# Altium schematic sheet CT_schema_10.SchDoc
size 391 x 278 mm
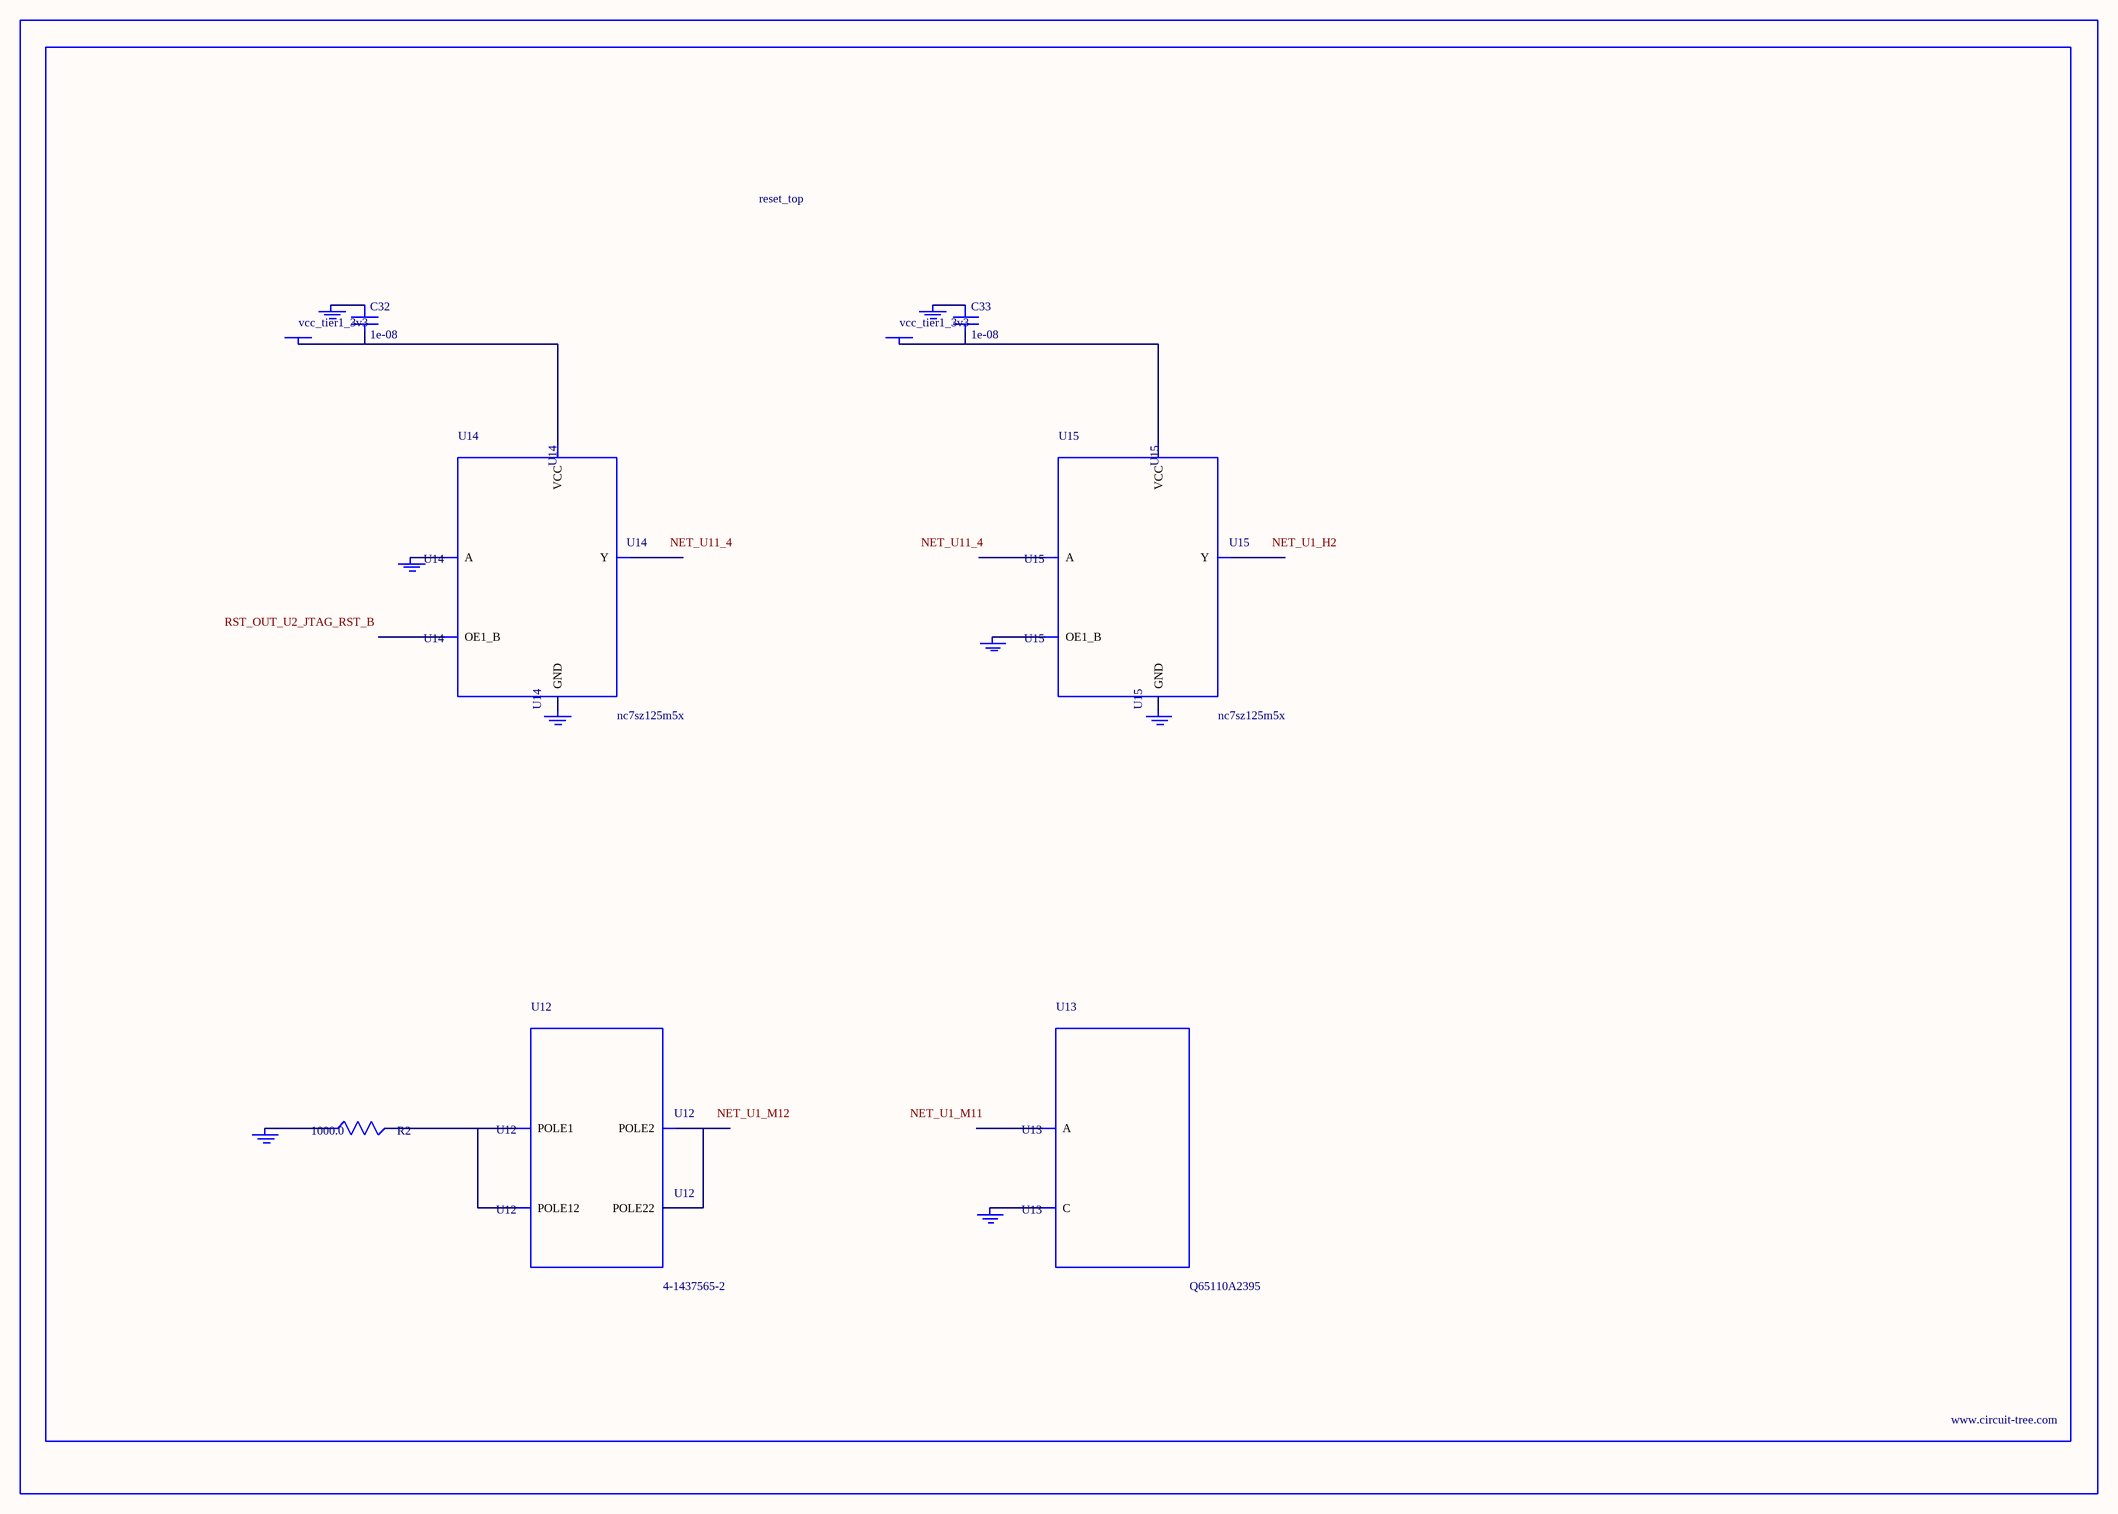
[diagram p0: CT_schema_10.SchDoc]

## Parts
BORDER9  (no value)
C32  1e-08  [C0402]
C33  1e-08  [C0402]
GND_INSTANCE_9_0  (no value)
GND_INSTANCE_9_1  (no value)
GND_INSTANCE_9_2  (no value)
GND_INSTANCE_9_3  (no value)
GND_INSTANCE_9_4  (no value)
GND_INSTANCE_9_5  (no value)
GND_INSTANCE_9_6  (no value)
GND_INSTANCE_9_7  (no value)
POWER_INSTANCE_9_0  vcc_tier1_3v3
POWER_INSTANCE_9_1  vcc_tier1_3v3
R2  1000.0  [R0603]
U12  4-1437565-2  [SW_4-1437565-2]
U13  Q65110A2395  [LGM67K-G1J2-24-Z]
U14  nc7sz125m5x  [NC7SZ125M5X]
U15  nc7sz125m5x  [NC7SZ125M5X]

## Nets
NetC32_1: C32.1 GND_INSTANCE_9_2.0(GND)
NetC32_2: C32.2 POWER_INSTANCE_9_0.0(PWR) U14.5(VCC)
NetC33_1: C33.1 GND_INSTANCE_9_5.0(GND)
NetC33_2: C33.2 POWER_INSTANCE_9_1.0(PWR) U15.5(VCC)
NetGND_INSTANCE_9_0_0: GND_INSTANCE_9_0.0(GND) R2.1
NetGND_INSTANCE_9_1_0: GND_INSTANCE_9_1.0(GND) U13.C
NetGND_INSTANCE_9_3_0: GND_INSTANCE_9_3.0(GND) U14.2(A)
NetGND_INSTANCE_9_4_0: GND_INSTANCE_9_4.0(GND) U14.3(GND)
NetGND_INSTANCE_9_6_0: GND_INSTANCE_9_6.0(GND) U15.1(OE1_B)
NetGND_INSTANCE_9_7_0: GND_INSTANCE_9_7.0(GND) U15.3(GND)
NetR2_2: R2.2 U12.1(POLE1) U12.2(POLE12)
NetU12_3: U12.3(POLE2) U12.4(POLE22)

Not connected (* = marked no-connect by the designer): U13 A; U14 1(OE1_B) 4(Y); U15 2(A) 4(Y)

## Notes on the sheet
- Labels drawn without touching a wire or pin: NET_U1_H2, NET_U1_M11, NET_U1_M12, NET_U11_4, RST_OUT_U2_JTAG_RST_B

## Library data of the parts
BORDER9 = BORDER_PAGE9
C32 C33 = C0402C103K3RAC
GND_INSTANCE_9_0-GND_INSTANCE_9_7 = GND
POWER_INSTANCE_9_0 POWER_INSTANCE_9_1 = PWR
R2 = RC0603JR-071KL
